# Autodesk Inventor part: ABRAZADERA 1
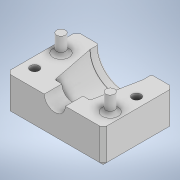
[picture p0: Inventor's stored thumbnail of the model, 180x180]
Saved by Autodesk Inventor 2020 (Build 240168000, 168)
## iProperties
Created: 2022-10
Part Number: ABRAZADERA 1
Material: Genérico
Document SubType Name: Modeling
Designer: SEBAS
Density: 1 g/cm^3
Appearance: Valor por defecto
Author: SEBAS
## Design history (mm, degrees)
sketch "Boceto1"
  geometry: L1 (0, 0)-(0, 40); L2 (0, 40)-(33, 40); L3 (33, 40)-(33, 30); L4 (33, 30)-(23, 30); L5 (23, 30)-(18, 5); L6 (18, 5)-(18, 0); L7 (18, 0)-(0, 0); L8 (33, 40)-(33, 0)
  constraints: 16 end point, 3 perpendicular, 2 horizontal, 2 vertical
  dimensions: "d0" = 40 distance of L1.start L1.end; "d1" = 10 distance of L2.end L3.end; "d2" = 5 horizontal distance of L4.end L5.end; "d3" = 25 vertical distance of L5.end L4.end; "d4" = 33 distance between parallel lines of L1 L3; "d5" = 18 distance of L1.start L6.end
revolve "Revolución1" sketch "Boceto1" stored, may be unused: angle "d6" = 180 deg
sketch "Boceto2"
  geometry: L1 (10, 0)-(-10, 0) reference; C1 r 6 at (0, 0); 3 further points
  constraints: 1 centre point, 1 midpoint
  dimensions: "d7" = 12 diameter of C1
extrude "Extrusión1" cut sketch "Boceto2" distance "d8" = 10; taper "d9" = 0 deg
sketch "Boceto3"
  geometry: L1 (11.5, -15)-(54.5, -15); C1 r 2.5 at (11.5, -15); C2 r 2.5 at (11.5, -30); C3 r 2.5 at (54.5, -15); C4 r 2.5 at (54.5, -30); 2 further points
  constraints: 4 centre point, 3 equal radius, 3 vertical alignment, 2 end point, 2 horizontal alignment, 1 horizontal, 1 midpoint
  dimensions: "d10" = 5 diameter of C1; "d11" = 15 vertical distance of point (33, 0) L1.start; "d12" = 15 distance of C2.centre L1.start; "d13" = 43 distance of L1.end L1.start
extrude "Extrusión2" join sketch "Boceto3" distance "d14" = 10; taper "d15" = 0 deg
extrude "Extrusión3" cut sketch "Boceto3" distance "d16" = 30; taper "d17" = 0 deg
sketch "Boceto4"
  geometry: L1 (66, 0)-(0, 0); L2 (0, 0)-(0, -20); L3 (0, -20)-(66, -20); L4 (66, -20)-(66, 0); L5 (66, -20)-(0, -20); L6 (0, -20)-(0, -39); L7 (0, -39)-(66, -39); L8 (66, -39)-(66, -20); A1 r 33 centre (33, 0) between (0, 0) and (66, 0) reference; 4 further points
  constraints: 16 end point, 4 parallel, 2 horizontal, 2 perpendicular, 1 tangent, 1 vertical alignment
  dimensions: "d18" = 20 distance of L3.end L1.start; "d19" = 19 distance of L7.end L3.end
extrude "Extrusión4" cut sketch "Boceto4" stored distance "d20" = 30; taper "d21" = 0 deg
extrude "Extrusión5" join sketch "Boceto4" stored distance "d22" = 30; taper "d23" = 0 deg
sketch "Boceto5"
  geometry: L1 (33, 0)-(6, 0) reference; L2 (-33, -20)-(33, -20) reference; L3 (27.5, 0)-(-27.5, 0); L4 (-27.5, 0)-(-27.5, -20); L5 (-27.5, -20)-(27.5, -20); L6 (27.5, -20)-(27.5, 0); L7 (33, -20)-(27.5, -20); L8 (27.5, -20)-(27.5, 0); L9 (27.5, 0)-(33, 0); L10 (33, 0)-(33, -20); L11 (-27.5, -20)-(-33, -20); L12 (-33, -20)-(-33, 0); L13 (-33, 0)-(-27.5, 0); L14 (-27.5, 0)-(-27.5, -20); L15 (-33, 0)-(-33, -20) reference; 7 further points
  constraints: 24 end point, 6 parallel, 3 horizontal, 3 perpendicular, 3 point on line, 2 midpoint, 1 coincident, 1 vertical alignment
  dimensions: "d24" = 55 distance between parallel lines of L4 L6
extrude "Extrusión6" cut sketch "Boceto5" stored distance "d25" = 30; taper "d26" = 0 deg
chamfer "Chaflán1" distance "d27" = 2; stored, may be unused: second distance "d28" = 2, angle "d29" = 45 deg
fillet "Empalme1" dims "d30" = 2
fillet "Empalme2" dims "d31" = 1
node "Sólido1"
